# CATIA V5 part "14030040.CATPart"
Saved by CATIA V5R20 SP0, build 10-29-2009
Part number: 14030040
Definition: NONE
Nomenclature: 14030040
Source: Unknown
Description: 14030040
Bounding box of the stored display mesh (mm): x -20 to 80, y -29 to 18.906, z -19.1 to 19.1
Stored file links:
  C:\Users\Utente\Desktop\IO LAVORO\3D X SITO CF\X SITO\PLASTICA\RF2\14030040.CATPart
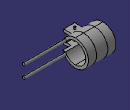
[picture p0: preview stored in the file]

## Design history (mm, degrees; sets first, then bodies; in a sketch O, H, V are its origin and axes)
Body1 "14030040" (main body)
  Solid1: solid without history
